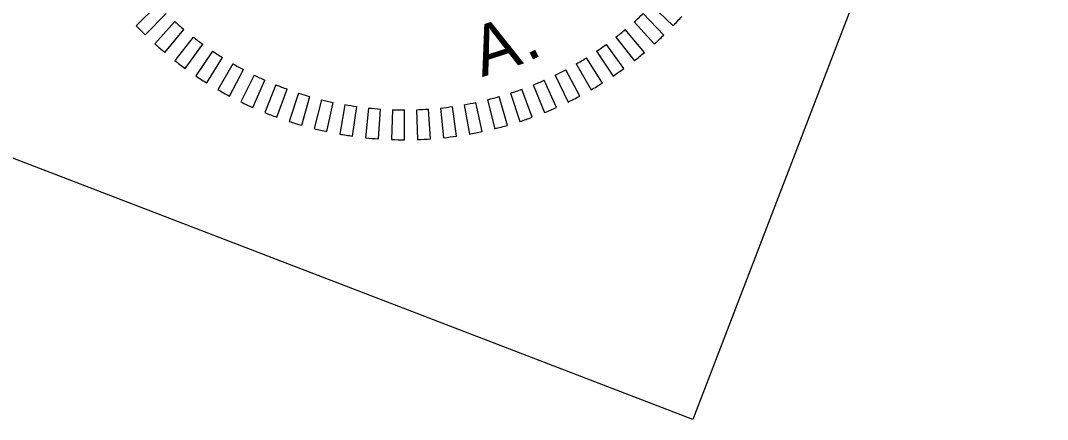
# Model space of a CAD drawing. Extents: x 1015221 to 1064345, y 619216 to 647967.
# Drawn here: x 1034182 to 1035013, y 641324 to 641647 of the extents above; entities that cross this region are included whole.
import ezdxf

# ---------------------------------------------------------------- set-up
doc = ezdxf.new("R2010")
doc.units = 0
doc.layers.add('Sheet PE Seal Cell', color=7, linetype='Continuous')
doc.layers.add('Sheet Plan CELL', color=7, linetype='Continuous')

msp = doc.modelspace()

# ---------------------------------------------------------------- linework, layer by layer
at = {"layer": 'Sheet PE Seal Cell'}
for p, q in [((1034292.92, 641659.68), (1034275.52, 641642.89)), ((1034692.83, 641659.56), (1034710.22, 641642.76)), ((1034282.98, 641635.43), (1034299.77, 641652.82)), ((1034702.76, 641635.31), (1034685.97, 641652.7)), ((1034306.87, 641646.2), (1034290.69, 641628.24)), ((1034678.87, 641646.09), (1034695.04, 641628.12)), ((1034298.65, 641621.32), (1034314.19, 641639.83)), ((1034687.08, 641621.2), (1034671.55, 641639.72)), ((1034321.73, 641633.72), (1034306.84, 641614.68)), ((1034315.26, 641608.33), (1034329.48, 641627.88)), ((1034670.46, 641608.22), (1034656.25, 641627.78)), ((1034664.01, 641633.62), (1034678.88, 641614.57)), ((1034337.42, 641622.31), (1034323.9, 641602.28)), ((1034648.31, 641622.22), (1034661.82, 641602.18)), ((1034332.74, 641596.53), (1034345.56, 641617.03)), ((1034353.87, 641612.03), (1034341.78, 641591.1)), ((1034631.85, 641611.94), (1034643.93, 641591.01)), ((1034652.97, 641596.43), (1034640.17, 641616.94)), ((1034351, 641585.98), (1034362.36, 641607.32)), ((1034371, 641602.91), (1034360.4, 641581.19)), ((1034614.71, 641602.84), (1034625.3, 641581.11)), ((1034634.7, 641585.9), (1034623.36, 641607.24)), ((1034369.96, 641576.73), (1034379.79, 641598.81)), ((1034388.72, 641595.01), (1034379.66, 641572.61)), ((1034596.99, 641594.95), (1034606.03, 641572.54)), ((1034615.74, 641576.66), (1034605.92, 641598.74)), ((1034389.51, 641568.82), (1034397.78, 641591.53)), ((1034406.95, 641588.37), (1034399.48, 641565.39)), ((1034409.56, 641562.3), (1034416.23, 641585.53)), ((1034576.13, 641562.25), (1034569.47, 641585.49)), ((1034578.75, 641588.32), (1034586.22, 641565.33)), ((1034596.19, 641568.76), (1034587.93, 641591.48)), ((1034425.6, 641583.02), (1034419.75, 641559.57)), ((1034430.02, 641557.19), (1034435.06, 641580.83)), ((1034444.58, 641578.98), (1034440.38, 641555.18)), ((1034450.79, 641553.52), (1034454.16, 641577.46)), ((1034463.79, 641576.27), (1034461.26, 641552.24)), ((1034521.91, 641576.26), (1034524.43, 641552.22)), ((1034534.89, 641553.5), (1034531.54, 641577.44)), ((1034541.12, 641578.95), (1034545.31, 641555.15)), ((1034555.66, 641557.15), (1034550.65, 641580.8)), ((1034560.1, 641582.98), (1034565.94, 641559.52)), ((1034471.77, 641551.31), (1034473.46, 641575.43)), ((1034483.15, 641574.91), (1034482.3, 641550.76)), ((1034492.84, 641550.57), (1034492.85, 641574.74)), ((1034502.55, 641574.91), (1034503.39, 641550.75)), ((1034513.92, 641551.3), (1034512.24, 641575.41))]:
    msp.add_line(p, q, dxfattribs=at)
for radius, start, end in [(277.97, 311.98294, 313.98294), (302.15, 223.98294, 225.98294), (277.97, 227.98294, 229.98294), (302.15, 315.98294, 317.98294), (277.97, 307.98294, 309.98294), (302.15, 311.98294, 313.98294), (302.15, 227.98294, 229.98294), (277.97, 231.98294, 233.98294), (277.97, 303.98294, 305.98294), (277.97, 235.98294, 237.98294), (302.15, 307.98294, 309.98294), (302.15, 231.98294, 233.98294), (277.97, 239.98294, 241.98294), (277.97, 299.98294, 301.98294), (302.15, 235.98294, 237.98294), (277.97, 243.98294, 245.98294), (277.97, 295.98294, 297.98294), (302.15, 303.98294, 305.98294), (277.97, 247.98294, 249.98294), (277.97, 291.98294, 293.98294), (302.15, 299.98294, 301.98294), (302.15, 239.98294, 241.98294), (277.97, 251.98294, 253.98294), (277.97, 283.98294, 285.98294), (277.97, 287.98294, 289.98294), (302.15, 295.98294, 297.98294), (302.15, 243.98294, 245.98294), (277.97, 255.98294, 257.98294), (277.97, 259.98294, 261.98294), (277.97, 263.98294, 265.98294), (277.97, 275.98294, 277.98294), (277.97, 279.98294, 281.98294), (302.15, 291.98294, 293.98294), (302.15, 247.98294, 249.98294), (277.97, 267.98294, 269.98294), (277.97, 271.98294, 273.98294), (302.15, 287.98294, 289.98294), (302.15, 251.98294, 253.98294), (302.15, 255.98294, 257.98294), (302.15, 283.98294, 285.98294), (302.15, 259.98294, 261.98294), (302.15, 263.98294, 265.98294), (302.15, 271.98294, 273.98294), (302.15, 275.98294, 277.98294), (302.15, 279.98294, 281.98294), (302.15, 267.98294, 269.98294)]:
    msp.add_arc((1034492.93, 641852.72), radius, start, end, dxfattribs=at)
at = {"layer": 'Sheet Plan CELL'}
msp.add_lwpolyline([(1033886.07, 641646.8), (1034173.12, 642393.95), (1035013.34, 642071.15), (1034726.15, 641324.16)], close=True, dxfattribs=at)

# ---------------------------------------------------------------- texts
at = {"layer": 'Sheet PE Seal Cell'}
for s, rotation, p in [('A', 18.27506, (1034555.57, 641601.16)), ('.', 26.87744, (1034592.49, 641613.36))]:
    msp.add_text(s, height=40.29, rotation=rotation, dxfattribs=at).set_placement(p)

doc.saveas('drawing.dxf')
